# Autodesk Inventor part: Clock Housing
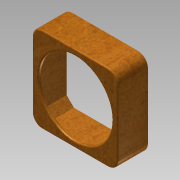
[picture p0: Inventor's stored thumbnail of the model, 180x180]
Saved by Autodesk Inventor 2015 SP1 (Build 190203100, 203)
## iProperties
Created: 2015-05
Part Number: Clock Housing
Material: PBT Plastic
Document SubType Name: Modeling
Designer: kazys
Density: 1.31 g/cm^3
Appearance: Yellow Pine - Solid Stained Light Low Gloss
Author: kazys
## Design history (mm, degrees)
sketch "Sketch1"
  geometry: L1 (-42.227, 42.228)-(42.227, 42.228); L2 (42.227, 42.228)-(42.227, -42.228); L3 (42.227, -42.228)-(-42.227, -42.228); L4 (-42.227, -42.228)-(-42.227, 42.228); L5 (-40.64, 30.988)-(-40.64, 12.152) reference; L6 (40.64, 12.152)-(40.64, 30.988) reference; L7 (30.988, 40.64)-(12.152, 40.64) reference; L8 (12.152, -40.64)-(30.988, -40.64) reference; 3 further points
  constraints: 8 end point, 2 midpoint, 2 parallel, 1 horizontal, 1 horizontal alignment, 1 perpendicular, 1 vertical alignment
  dimensions: "d0" = 1.5875 distance between parallel lines of L1 L7; "d1" = 1.5875 distance between parallel lines of L2 L6 (= d0)
extrude "Extrusion1" new body sketch "Sketch1" distance "d2" = 3.175; taper "d3" = 0 deg
sketch "Sketch2"
  geometry: C1 r 40.386 at (0, 0); 1 further point
  constraints: 1 centre point, 1 coincident
  dimensions: "d4" = 80.772 diameter of C1
extrude "Extrusion2" cut sketch "Sketch2" stored distance "d5" = 3.175; taper "d6" = 0 deg
sketch "Sketch3"
  geometry: L1 (-46.799, 46.8)-(46.799, 46.8); L2 (46.799, 46.8)-(46.799, -46.799); L3 (46.799, -46.799)-(-46.799, -46.8); L4 (-46.799, -46.8)-(-46.799, 46.8); L5 (-42.227, 42.228)-(-42.227, -42.228) reference; L6 (42.227, 42.228)-(-42.227, 42.228) reference; L7 (42.227, -42.228)-(42.227, 42.228) reference; L8 (-42.227, -42.228)-(42.227, -42.228) reference; 1 further point
  constraints: 8 end point, 2 parallel, 1 horizontal, 1 perpendicular
  dimensions: "d7" = 4.572 distance between parallel lines of L4 L5; "d8" = 4.572 distance between parallel lines of L1 L6 (= d7); "d9" = 4.572 distance between parallel lines of L2 L7 (= d7); "d10" = 4.572 distance between parallel lines of L3 L8 (= d7)
extrude "Extrusion3" join sketch "Sketch3" distance "d11" = 33.234 (computed from d2); taper "d12" = 0 deg
fillet "Fillet1" dims "d13" = 6.35
fillet "Fillet2" dims "d14" = 10.922 (= d13 + d7)
sketch "Sketch4"
  geometry: L1 (-43.849, -32.575)-(-32.575, -43.849); L2 (-32.575, -43.849)-(-40.261, -43.849); L3 (-40.261, -43.849)-(-43.849, -40.261); L4 (-43.849, -40.261)-(-43.849, -32.575); L5 (-46.799, 35.878)-(-46.799, -35.878) reference; L6 (-35.877, -46.799)-(35.877, -46.8) reference; A1 r 9.652 centre (-30.988, -30.988) between (-40.64, -30.988) and (-30.988, -40.64) reference; A2 r 6.35 centre (-35.877, -35.878) between (-42.227, -35.878) and (-35.877, -42.228) reference; 1 further point
  constraints: 8 end point, 1 horizontal, 1 parallel, 1 perpendicular
  dimensions: "d15" = 135 deg angle of L1 L2; "d16" = 3.302 distance from line of L1 A2.centre; "d17" = 14.224 distance from line of L5 L1.end; "d18" = 14.224 distance from line of L6 L1.start
extrude "Extrusion4" join sketch "Sketch4" stored distance "d19" = 25.4; taper "d20" = 0 deg
pattern_circular "Circular Pattern1" dims angle "d22" = 360 deg
sketch "Sketch5"
  geometry: L1 (-39.687, 39.687)-(39.688, -39.687); L2 (35.877, 46.8)-(-35.877, 46.8) reference; 4 further points
  constraints: 2 end point, 2 horizontal alignment, 2 vertical alignment, 1 coincident, 1 midpoint
  dimensions: "d24" = 45 deg angle of L2 L1; "d25" = 79.375 distance of point (39.688, 39.687) L1.start; "d26" = 79.375 distance of point (-39.687, -39.687) L1.start (derived)
hole "Hole1" sketch "Sketch5" at (-39.687, 39.687), (39.688, 39.687), (39.688, -39.687), (-39.687, -39.687) diameter "d27" = 3.175; stored, may be unused: countersink angle "d31" = 82 deg, drill point angle "d33" = 118 deg; dims "d28" = 19.05, "d29" = 9.525, "d30" = 6.35, "d32" = 12.7
fillet "Fillet3" dims "d34" = 1.524
fillet "Fillet4" dims "d35" = 1.524
body "Solid1"
node "Reference1"
node "Reference2"
node "Reference3"
node "Reference4"
node "Reference5"
